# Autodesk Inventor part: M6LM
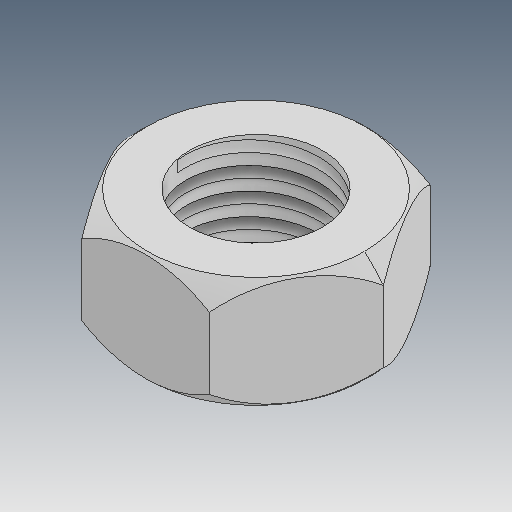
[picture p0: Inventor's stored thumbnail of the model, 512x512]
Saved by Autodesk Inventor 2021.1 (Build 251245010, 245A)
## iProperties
Created: 2019-04
Part Number: M6LM
Material: Ogólny
Document SubType Name: Modeling
Designer: user
Density: 1 g/cm^3
Appearance: Domyślna
Author: user
Revision Number: ÈÎºÎ
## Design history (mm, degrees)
feature "ÊäÈë1"
node "Bryła1"
